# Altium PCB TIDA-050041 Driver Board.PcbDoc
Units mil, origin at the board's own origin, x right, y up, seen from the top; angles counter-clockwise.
Board outline 3950.03 x 2770.03 mil, 2 copper layers (Top Layer, Bottom Layer), stack 62 mil thick; 45 components, 22 nets, 112 pads, 128 vias.
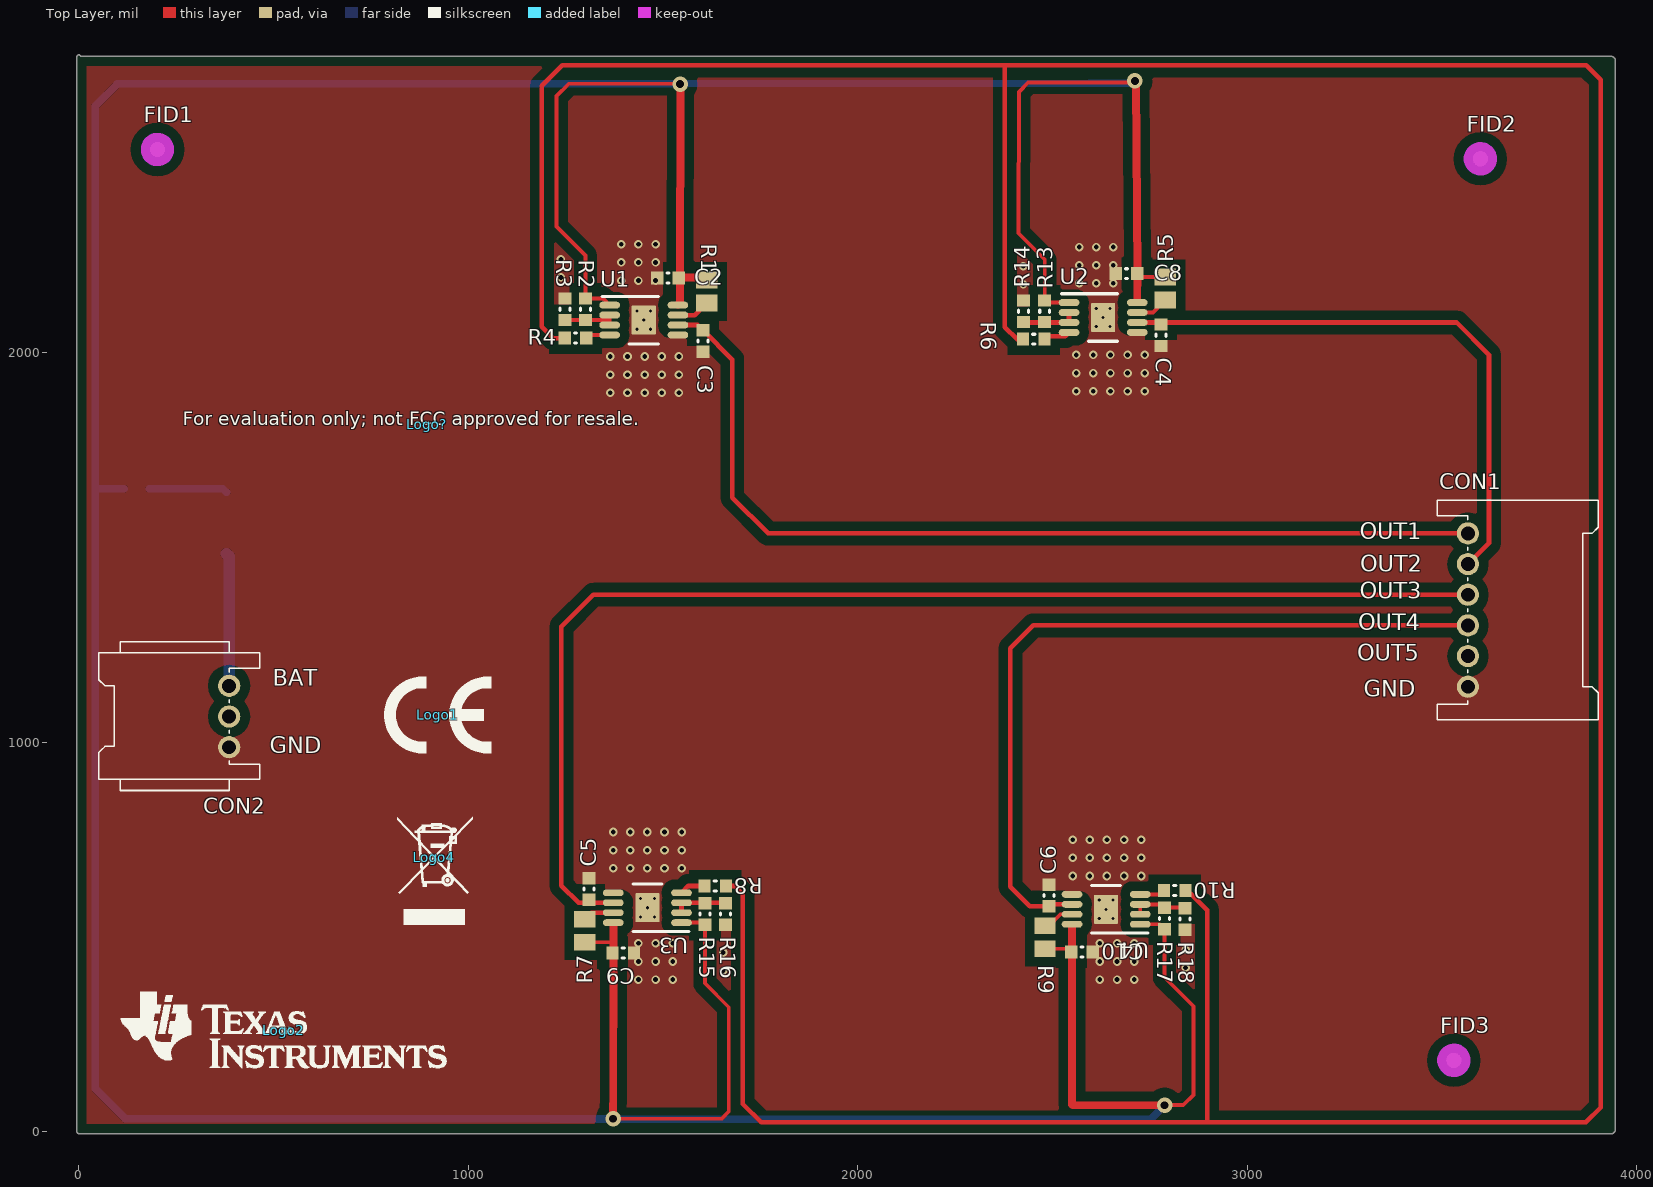
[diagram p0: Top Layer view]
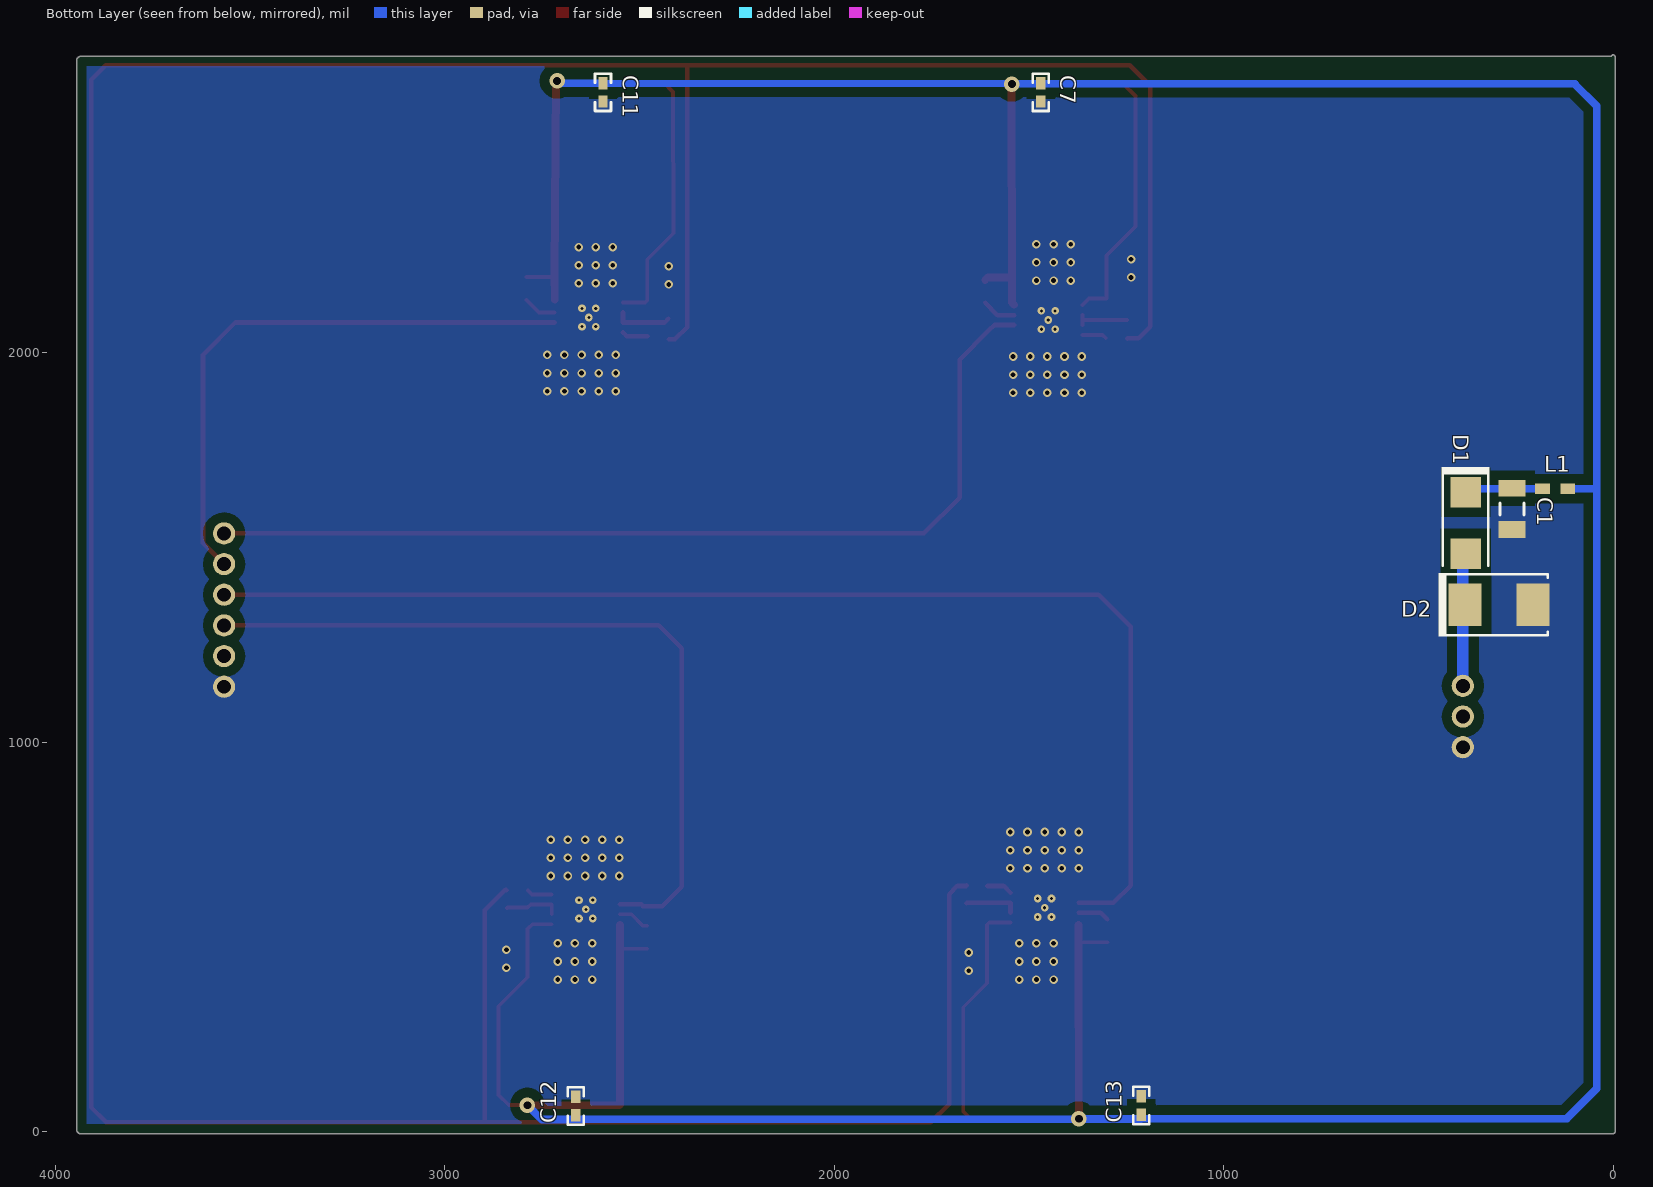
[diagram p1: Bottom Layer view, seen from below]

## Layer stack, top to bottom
Top Solder: solder mask 0.4, Solder Resist, Dk 3.5
Top Layer: signal copper 1.4
Dielectric1: core 59.2, FR-4, Dk 4.8
Bottom Layer: signal copper 1.4
Bottom Solder: solder mask 0.4, Solder Resist, Dk 3.5

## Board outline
0,-5.02 cw(c0,0) -5.01,0 -5.01,2760 cw(c0,2760) 4.93,2760.92 3937.01,2760.92 cw(c3937.01,2755.91) 3941.72,2757.62 cw(c3940,2752.91) 3945.02,2752.91 3945.02,2.99 cw(c3940,2.99) 3941.72,-1.72 cw(c3937.01,0) 3937.01,-5.02

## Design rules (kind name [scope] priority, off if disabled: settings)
AcuteAngle [All] p1: minimum=4.50000000000000E+0001 checktracksonly=FALSE
AssemblyTestPointUsage [All] p1: valid=2
BoardOutlineClearance BoardOutlineClearance_MountingHoles [OnCopper and InComponentClass('Mounting Holes')] p1: gap=40 ignorepadtopadclearanceinfootprint=FALSE
BoardOutlineClearance BoardOutlineClearance_Poly [OnCopper and IsPoly] p2: gap=25 ignorepadtopadclearanceinfootprint=FALSE
BoardOutlineClearance [OnCopper and Not InComponentClass('Logo') and not InComponentClass('FiducialMark') and not InRegion(1000,500,4000,800) and not InPoly] p3: gap=30 ignorepadtopadclearanceinfootprint=FALSE
Clearance Clearance_Keepouts [((IsTrack Or IsArc) And Not InPoly) And IsFree and IsKeepOut vs ((IsTrack Or IsArc) And Not InPoly) And IsFree and IsKeepOut] p1: gap=0 ignorepadtopadclearanceinfootprint=FALSE
Clearance Clearance_Poly [InPolygon] p2: gap=25 ignorepadtopadclearanceinfootprint=FALSE except(0: Arc-Hole Track-Hole SMDPad-Hole THPad-Hole Via-Hole Fill-Hole Poly-Hole Region-Hole Text-Hole)
Clearance Clearance_FiducialMark [IsKeepOut and InComponentClass('FiducialMark') vs IsPad and InComponentClass('FiducialMark')] p3: gap=0 ignorepadtopadclearanceinfootprint=FALSE
Clearance [All] p4: gap=7.87 ignorepadtopadclearanceinfootprint=FALSE except(0: Arc-Hole Track-Hole SMDPad-Hole THPad-Hole Via-Hole Fill-Hole Poly-Hole Region-Hole Text-Hole)
ComponentClearance ComponentClearance_MountingHoles_FiducialMarks [InComponentClass('Mounting Holes') vs InComponentClass('FiducialMark')] p1: gap=50 collisioncheckmode=3 verticalgap=10 showdistances=FALSE
ComponentClearance ComponentClearance_Shunt [InComponentClass('Header') vs InComponentClass('Shunt')] p2: gap=0 collisioncheckmode=3 verticalgap=0 showdistances=FALSE
ComponentClearance ComponentClearance_Logo [InComponentClass('Logo')] p3: gap=50 collisioncheckmode=3 verticalgap=10 showdistances=FALSE
ComponentClearance ComponentClearance_ScrewToNut [(HasFootprint('NY PMS 440 0025 PH')) vs (HasFootprint('Keystone_1902C'))] p4: gap=5 collisioncheckmode=3 verticalgap=10 showdistances=FALSE
ComponentClearance ComponentClearance_MountingHoles [InComponentClass('Mounting Holes')] p5: gap=250 collisioncheckmode=3 verticalgap=100000 showdistances=FALSE
ComponentClearance ComponentClearance_SmallPassives [HasFootprint('0201*') or HasFootprint('0402*') or HasFootprint('0508') or HasFootprint('0603*') or HasFootprint('0612') or HasFootprint('0805*') or HasFootprint('0815*') or HasFootprint('0830*') or HasFootprint('1206*') or HasFootprint('1210*') or HasFootprint('1808*') or HasFootprint('1812*') or HasFootprint('1825*') or HasFootprint('2010*') or HasFootprint('2220*') or HasFootprint('2225*') or HasFootprint('2512*') or HasFootprint('2728*') or HasFootprint('3518*') vs HasFootprint('0201*') or HasFootprint('0402*') or HasFootprint('0508') or HasFootprint('0603*') or HasFootprint('0612') or HasFootprint('0805*') or HasFootprint('0815*') or HasFootprint('0830*') or HasFootprint('1206*') or HasFootprint('1210*') or HasFootprint('1808*') or HasFootprint('1812*') or HasFootprint('1825*') or HasFootprint('2010*') or HasFootprint('2220*') or HasFootprint('2225*') or HasFootprint('2512*') or HasFootprint('2728*') or HasFootprint('3518*')] p6: gap=14.96 collisioncheckmode=3 verticalgap=10 showdistances=FALSE
ComponentClearance ComponentClearance_THtoSMT [IsThruComponent vs IsSMTComponent] p7: gap=40 collisioncheckmode=3 verticalgap=30 showdistances=FALSE
ComponentClearance ComponentClearance_THtoTH [IsThruComponent vs IsThruComponent] p8: gap=30 collisioncheckmode=3 verticalgap=30 showdistances=FALSE
ComponentClearance [All] p9: gap=30 collisioncheckmode=3 verticalgap=10 showdistances=FALSE
DiffPairsRouting [All] p1: maxlimit=100 minlimit=10 mostfreqgap=10 toplayer_minwidth=15 toplayer_maxwidth=15 toplayer_prefwidth=15 bottomlayer_minwidth=15 bottomlayer_maxwidth=15 bottomlayer_prefwidth=15 maxuncoupledlength=1000
FabricationTestPointUsage TestPointUsage [All] p1: valid=2 allowmultiple=FALSE
FabricationTestpoint Testpoint [All] p1: side=3 testpointundercomponent=TRUE minsize=40 maxsize=100 preferedsize=60 minholesize=0 maxholesize=40 preferedholesize=32 testpointgrid=1 allowsidetop=TRUE allowsidebottom=TRUE usegrid=TRUE gridtolerance=0.01
FanoutControl Fanout_LCC [IsLCC] p1: bgadir=Out bgaviamode=Centered fanoutstyle=Auto fanoutdirection=Alternating viagrid=1 // Fanout_LCC (Default Rule)
FanoutControl Fanout_BGA [IsBGA] p2: bgadir=Out bgaviamode=Centered fanoutstyle=Auto fanoutdirection=Alternating viagrid=1 // Fanout_BGA (Default Rule)
FanoutControl Fanout_Default [All] p4: bgadir=Out bgaviamode=Centered fanoutstyle=Auto fanoutdirection=Alternating viagrid=1 // Fanout_Default (Default Rule)
FanoutControl Fanout_Small [(CompPinCount < 5)] p5: bgadir=Out bgaviamode=Centered fanoutstyle=Auto fanoutdirection=OutThenIn viagrid=1 // Fanout_Small (Default Rule)
HoleSize [All] p1: absolutevalues=TRUE maxlimit=251 minlimit=7.87 maxpercent=80.000 minpercent=20.000
MinimumAnnularRing MinimumAnnularRing_ThermalPadVias [IsVia and InAnyComponent] p1: minimumring=5.91
MinimumAnnularRing [All] p2: minimumring=8
MinimumSolderMaskSliver MinimumSolderMaskSliver_Logo [InComponentClass('Logo') vs InComponentClass('Logo')] p1: minsoldermaskwidth=0.7
MinimumSolderMaskSliver [All] p2: minsoldermaskwidth=3.94
PlaneConnect [All] p1: planeconnectstyle=Direct reliefexpansion=10 reliefentries=4 reliefconductorwidth=10 reliefairgap=10
PolygonConnect [All] p1: connectstyle=Direct reliefconductorwidth=10 reliefentries=4 polygonreliefangle="90 Angle" airgapwidth=10
RoutingVias ThermalPadVias [IsVia and InAnyComponent] p1: holewidth=7.87 width=19.68 viastyle="Through Hole" minholewidth=7.87 minwidth=19.68 maxholewidth=12.99 maxwidth=23.62
RoutingVias [All] p2: holewidth=16 width=34 viastyle="Through Hole" minholewidth=7.87 minwidth=26 maxholewidth=40 maxwidth=65
SilkToBoardRegionClearance [Not ((IsComment or IsDesignator) And (Hide <> 'False')) and not InRegion(1000,500,4000,800)] p1:
SilkToSilkClearance SilkToSilkClearance_Pb-FreeLogo [(HasFootprint('Pb-Free_Overlay_Medium') OR HasFootprint('Pb-Free_Overlay_Small')) vs (HasFootprint('Pb-Free_Overlay_Medium') OR HasFootprint('Pb-Free_Overlay_Small'))] p1: silktosilkclearance=0
SilkToSilkClearance [All] p2: silktosilkclearance=4
SilkToSolderMaskClearance SilkToComponentPadClearance [(IsPad or IsFill or IsRegion) and InAnycomponent] p1: minsilkscreentomaskgap=5 clearancetoexposedcopper=TRUE
SilkToSolderMaskClearance "Silk to Solder Mask Opening" [All] p2: minsilkscreentomaskgap=4 clearancetoexposedcopper=FALSE
SolderMaskExpansion [All] p1: expansion=1.97
Width [All] p1: maxlimit=100 minlimit=6 preferedwidth=10 checkconnectedcopper=TRUE
15 further rules are at their usual default settings.

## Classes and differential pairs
component class Sheet1: FID1 FID2 FID3 Logo1 Logo2 Logo4 Logo?
component class Logo: Logo2
component class FiducialMark: FID1 FID2 FID3
component class "TIDA-050041 Driver Board": C1 C2 C3 C4 C5 C6 C7 C8 C9 C10 C11 C12 C13 CON1 CON2 D1 D2 L1 R1 R2 R3 R4 R5 R6 R7 R8 R9 R10 R13 R14 R15 R16 R17 R18 U1 U2 U3 U4

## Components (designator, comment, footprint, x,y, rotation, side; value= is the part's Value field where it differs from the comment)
C1 "GRM319R61H475KA12" 1206L 260,1599 r270 bottom value=4.7uF
C2 "CGA3E3X8R1H104K080AE" 0603L 1513,2192 r180 top value=0.1uF
C3 "CGA3E3X8R1H104K080AE" 0603L 1603,2030.13 r270 top value=0.1uF
C4 "CGA3E3X8R1H104K080AE" 0603L 2779,2045 r270 top value=0.1uF
C5 "CGA3E3X8R1H104K080AE" 0603L 1310,623 r90 top value=0.1uF
C6 "CGA3E3X8R1H104K080AE" 0603L 2491.4,606.55 r90 top value=0.1uF
C7 "GRM155R71H471KA01D" 0402 1470,2668.62 r270 bottom value=470pF
C8 "CGA3E3X8R1H104K080AE" 0603L 2690,2203 r180 top value=0.1uF
C9 "CGA3E3X8R1H104K080AE" 0603L 1398,459 r0 top value=0.1uF
C10 "CGA3E3X8R1H104K080AE" 0603L 2576,461 r0 top value=0.1uF
C11 "GRM155R71H471KA01D" 0402 2594,2668.62 r270 bottom value=470pF
C12 "GRM155R71H471KA01D" 0402 2664,66 r90 bottom value=470pF
C13 "GRM155R71H471KA01D" 0402 1212,67 r90 bottom value=470pF
CON1 "SWB-3535WR-06B-NOSN" "SWB-3535 WR-06P" 3567,1142.52 r90 top
CON2 "SWB-3535WR-03B-NOSN" "SWB-3535 WR-03P" 386,1066 r270 top
D1 "S1A" SMA 379,1563 r270 bottom value=50V
D2 "SMBJ30CA-13-F" SMB 293,1353 r180 bottom value=30V
FID1 "Fiducial" Fiducial10-20 202,2522 r0 top
FID2 "Fiducial" Fiducial10-20 3599,2498 r0 top
FID3 "Fiducial" Fiducial10-20 3531,183 r0 top
L1 "74279266A" WE-CBF_0603 149,1651 r180 bottom value="1000 ohm"
Logo1 "CE Mark" CE_Mark_5mm 921.85,1070 r0 top
Logo2 "Texas Instruments" TI_Stacked_Overlay_Small 526,261 r0 top
Logo4 "WEEE logo" WEEE_Minimum 912.76,704 r0 top
Logo? "FCC disclaimer" FCC_disclaimer 894,1816 r0 top
R1 "RMCF0805FT1R00" 0805L 1612.37,2157.65 r270 top value=1.00
R2 "RC0603FR-0775KL" 0603L 1301.37,2111.65 r90 top value=75.0k
R3 "CRCW060320K0FKEA" 0603L 1248.37,2111.65 r270 top value=20.0k
R4 "ERJ-3GEY0R00V" 0603L 1275.37,2037.65 r180 top value=0
R5 "RMCF0805FT1R00" 0805L 2790.28,2164.62 r270 top value=1.00
R6 "ERJ-3GEY0R00V" 0603L 2452.28,2034.83 r180 top value=0
R7 "RMCF0805FT1R00" 0805L 1299,516 r90 top value=1.00
R8 "ERJ-3GEY0R00V" 0603L 1634.5,630.95 r0 top value=0
R9 "RMCF0805FT1R00" 0805L 2481,499.06 r90 top value=1.00
R10 "ERJ-3GEY0R00V" 0603L 2814.4,619.55 r0 top value=0
R13 "RC0603FR-0775KL" 0603L 2480.28,2106.62 r90 top value=75.0k
R14 "CRCW060320K0FKEA" 0603L 2426.28,2106.62 r270 top value=20.0k
R15 "RC0603FR-0775KL" 0603L 1607.5,558.95 r270 top value=75.0k
R16 "CRCW060320K0FKEA" 0603L 1660.5,558.95 r90 top value=20.0k
R17 "RC0603FR-0775KL" 0603L 2787.4,547.55 r270 top value=75.0k
R18 "CRCW060320K0FKEA" 0603L 2840.4,546.31 r90 top value=20.0k
U1 "TPS92611QDGNRQ1" DGN0008D_N 1450.68,2084 r0 top
U2 "TPS92611QDGNRQ1" DGN0008D_N 2630.28,2090.62 r0 top
U3 "TPS92611QDGNRQ1" DGN0008D_N 1460,575 r180 top
U4 "TPS92611QDGNRQ1" DGN0008D_N 2638,571 r180 top

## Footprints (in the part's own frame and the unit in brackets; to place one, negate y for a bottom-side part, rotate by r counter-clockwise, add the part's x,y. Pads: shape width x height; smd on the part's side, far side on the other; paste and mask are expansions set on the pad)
0402 [mm] "0402 from SM-752 data"
  rect 0.8x0.6 smd: 1(-0.6,0) 2(0.6,0)
  silkscreen extent -1.22,-0.52 1.22,0.52, body extent -0.55,-0.3 0.55,0.3, height 0.6
0603L [mm] "0603 from SM-752 data"
  rect 0.8x0.85 smd: 1(-0.7,0) 2(0.7,0)
  silkscreen extent -0.07,-0.33 0.07,0.33, body extent -0.87,-0.47 0.87,0.47, height 1
0805L [mm] "0805 from SM-752 data"
  rect 1.1x1.4 smd: 1(-0.75,0) 2(0.75,0)
  body extent -1.1,-0.72 1.1,0.72, height 1.45
1206L [mm] "1206 from SM-752 data"
  rect 1.1x1.75 smd: 1(-1.35,0) 2(1.35,0)
  silkscreen extent -0.4,-0.77 0.4,0.77, body extent -1.7,-0.9 1.7,0.9, height 1.35
CE_Mark_5mm [mil] "Minimum text height for CE Mark"
  silkscreen extent -138,-98 138,98
DGN0008D_N [mm] "TSOP, 8-Leads, Body 3x3mm, Pitch 0.65mm, Thermal Pad 1.89x1.57mm, IPC Medium Density"
  rrect100% 1.35x0.45 smd: 1(-2.225,0.975) 2(-2.225,0.325) 3(-2.225,-0.325) 4(-2.225,-0.975) 5(2.225,-0.975) 6(2.225,-0.325) 7(2.225,0.325) 8(2.225,0.975)
  rrect6% 1.57x1.89 smd: 9(0,0)
  silkscreen extent -2.73,-1.55 0.95,1.55, body extent -2.46,-1.5 2.46,1.5, height 1.1
FCC_disclaimer [mil]
Fiducial10-20 [mm]
  round 1 smd mask+0.5: 1(0,0)
  Top Layer keep-out circle w1.178: c0,0 r0.5
SMA [mm] "Molded Diode, 2-Leads, Body 4.3x2.6mm, IPC Medium Density, based on OnSemi component dimensions and land pattern"
  rect 2x2 smd: 1(-2,0) 2(2,0)
  silkscreen extent -3.66,-1.57 2.79,1.57, body extent -2.6,-1.3 2.6,1.3, height 2.42
SMB [mil] "Molded Diode, 2-Leads, Body 5.4x3.6mm, IPC Medium Density, based on OnSemi component dimensions"
  rect 85x107.99 smd: 1(-87.01,0) 2(87.01,0)
  silkscreen extent -155,-82 125,82, body extent -106,-71 106,71, height 91
"SWB-3535 WR-03P" [mm]
  round 1.45 hole 0.9: 1(-2,0) 2(0,0) 3(2,0)
  silkscreen extent -4.88,-8.5 4.83,2, body extent -4.85,-8.5 4.85,2, height 5.65
"SWB-3535 WR-06P" [mm]
  round 1.45 hole 0.9: 1(0,0) 2(2,0) 3(4,0) 4(6,0) 5(8,0) 6(10,0)
  silkscreen extent -2.15,-8.5 12.15,2, body extent -2.15,-8.5 12.15,2, height 5.65
TI_Stacked_Overlay_Small [mil]
  silkscreen extent -418,-98 418,98
WE-CBF_0603 [mm] "WE_SMT-0603"
  rect 0.95x0.7 smd: 1(-0.825,0) 2(0.825,0)
  body extent -0.9,-0.5 0.9,0.5, height 1
WEEE_Minimum [mil] "WEEElie bin"
  silkscreen extent -95,-172 99,104

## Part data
C1: library part CMP-0008865-2, "CAP, CERM, 4.7 uF, 50 V, +/- 10%, X5R, 1206", Cap_Case=1206, Manufacturer=MuRata, Supplier Part Number 1=13T1225, TempCo=X5R, Tolerance_%=10%, Value1=Unknown, Value2=50V, ValueDisplayed=4.7uF
C2 C3 C4 C5 C6 C8 C9 C10: library part CMP-0079911-1, "CAP, CERM, 0.1 礔, 50 V,+/- 10%, X8R, AEC-Q200 Grade 0, 0603", Cap_Case=0603, Manufacturer=TDK, Supplier Part Number 1=445-173697-1-ND, TempCo=X8R, Tolerance_%=10%, Value2=50V, ValueDisplayed=0.1礔
C7 C11 C12 C13: library part CMP-0006691-2, "CAP, CERM, 470 pF, 50 V, +/- 10%, X7R, 0402", Cap_Case=0402, Manufacturer=MuRata, Supplier Part Number 1=490-1300-1-ND, TempCo=X7R, Tolerance_%=10%, Value1=Unknown, Value2=50V, ValueDisplayed=470pF
CON1 CON2: 供覽]商/品牌 Manufacturer=SWB
D1: library part CMP-0082549-1, "Diode, Standard Recovery Rectifier, 50 V, 1 A, SMA", Manufacturer="ON Semiconductor", Supplier Part Number 1=S1AFSCT-ND, Value1=1A, Value2=1.1V
D2: library part CMP-0005562-2, "Diode, TVS, Bi, 30 V, SMB", Manufacturer="Diodes Inc.", Power_W=5W, Supplier Part Number 1=SMBJ30CA-FDICT-ND
FID1 FID2 FID3: library part CMP-0077181-1, "Fiducial mark.  There is nothing to buy or mount.", Manufacturer=N/A
L1: library part CMP-0003204-1, "Ferrite Bead, 1000 ohm @ 100 MHz, 0.2 A, 0603", Manufacturer="Wurth Elektronik", Supplier Part Number 1=732-1598-1-ND, Value1="0.6 ohm", Value2=0.2A, ValueDisplayed="1000 ohm"
Logo1: library part CMP-0074844-1
Logo2: library part CMP-0074838-1, "Texas Instrument Corporate Signature"
Logo4: library part CMP-0074769-1
Logo?: library part CMP-0074847-1, "FCC_disclaimer"
R1 R5 R7 R9: library part CMP-0021975-2, "RES, 1.00, 1%, 0.125 W, 0805", Manufacturer="Stackpole Electronics Inc", Power_W=125mW, Supplier Part Number 1=RMCF0805FT1R00DKR-ND, TempCo="200 ppm/C", Tolerance_%=1%, Value2=0.125W, Value_Code=1R00, ValueDisplayed=1.00
R2 R13 R15 R17: library part CMP-0023267-5, "RES, 75.0 k, 1%, 0.1 W, 0603", Manufacturer=Yageo, Power_W=100mW, Supplier Part Number 1=311-75.0KHRCT-ND, TempCo="100 ppm/C", Tolerance_%=1%, Value2=0.1W, Value_Code=75k0, ValueDisplayed=75.0k
R3 R14 R16 R18: library part CMP-0022204-4, "RES, 20.0 k, 1%, 0.1 W, AEC-Q200 Grade 0, 0603", Manufacturer=Vishay-Dale, Power_W=100mW, Supplier Part Number 1=541-20.0KHCT-ND, TempCo="100 ppm/C", Tolerance_%=1%, Value2=0.1W, Value_Code=20k0, ValueDisplayed=20.0k
R4 R6 R8 R10: library part CMP-0025874-4, "RES, 0, 5%, 0.1 W, AEC-Q200 Grade 0, 0603", Manufacturer=Panasonic, Power_W=100mW, Supplier Part Number 1=P0.0GCT-ND, TempCo="600 ppm/C", Tolerance_%=5%, Value2=0.1W, Value_Code=0000, ValueDisplayed=0
U1 U2 U3 U4: library part CMP-0065147-2, "Automotive Single Channel LED Driver, DGN0008D (VSSOP-8)", Alternate Manufacturer="Texas Instruments"

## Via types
v1: diameter 22, hole 12, Top Layer to Bottom Layer, 104 vias
v2: diameter 19.68, hole 7.87, Top Layer to Bottom Layer, 20 vias
v3: diameter 40, hole 20, Top Layer to Bottom Layer, 4 vias

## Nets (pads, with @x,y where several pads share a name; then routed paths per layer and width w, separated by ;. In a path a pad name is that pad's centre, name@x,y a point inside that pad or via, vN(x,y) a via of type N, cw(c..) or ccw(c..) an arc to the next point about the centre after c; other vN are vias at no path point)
BAT: CON2.1 D1.2 D2.1 | length 342.4
  Bottom Layer w30: D1.2 386,1477.26 CON2.1
GND: C1.2 C2.2 C3.2 C4.2 C5.2 C6.2 C7.2 C8.2 C9.2 C10.2 C11.2 C12.2 C13.2 CON1.1 CON2.3 D2.2 R3.1 R14.1 R16.1 R18.1 U1.5 U1.9 U2.5 U2.9 U3.5 U3.9 U4.5 U4.9
  other v1: 1437,390.5 1481,390.5 1525,390.5 2622,390.5 2666,390.5 2710,390.5 1655,413.5 2841.96,420.5 1437,437 1481,437 1525,437 2622,437 2666,437 2710,437 1655,460 2841.96,467 1437,483.5 1481,483.5 1525,483.5 2622,483.5 2666,483.5 2710,483.5 2552,656.5 2596,656.5 2640,656.5 2684,656.5 2728,656.5 1372,676.5 1416,676.5 1460,676.5 1504,676.5 1548,676.5 2552,703 2596,703 2640,703 2684,703 2728,703 1372,723 1416,723 1460,723 1504,723 1548,723 2552,749.5 2596,749.5 2640,749.5 2684,749.5 2728,749.5 1372,769.5 1416,769.5 1460,769.5 1504,769.5 1548,769.5 1365,1897.5 1409,1897.5 1453,1897.5 1497,1897.5 1541,1897.5 2561,1901.5 2605,1901.5 2649,1901.5 2693,1901.5 2737,1901.5 1365,1944 1409,1944 1453,1944 1497,1944 1541,1944 2561,1948 2605,1948 2649,1948 2693,1948 2737,1948 1365,1990.5 1409,1990.5 1453,1990.5 1497,1990.5 1541,1990.5 2561,1994.5 2605,1994.5 2649,1994.5 2693,1994.5 2737,1994.5 2425,2175.5 2568.57,2178.5 2612.57,2178.5 2656.57,2178.5 1393,2185.5 1437,2185.5 1481,2185.5 1238,2193.5 2425,2222 2568.57,2225 2612.57,2225 2656.57,2225 1393,2232 1437,2232 1481,2232 1238,2240 2568.57,2271.5 2612.57,2271.5 2656.57,2271.5 1393,2278.5 1437,2278.5 1481,2278.5
  other v2: 2620.28,547.38 2655.72,547.38 1442.28,551.38 1477.72,551.38 2638,571 1460,575 2620.28,594.62 2655.72,594.62 1442.28,598.62 1477.72,598.62 1432.97,2060.38 1468.4,2060.38 2612.57,2067 2648,2067 1450.68,2084 2630.28,2090.62 1432.97,2107.62 1468.4,2107.62 2612.57,2114.24 2648,2114.24
IN: C2.1 C7.1 C8.1 C9.1 C10.1 C11.1 C12.1 C13.1 L1.2 R1.1 R2.2 R5.1 R7.1 R9.1 R13.2 R15.2 R17.2 U1.1 U1.8 U2.1 U2.8 U3.1 U3.8 U4.1 U4.8 | length 14069.3
  Top Layer w10: R7.1 1372.37,486.47 1372.84,486 ; U1.1 1346.27,2139.2 R2.2 1301.37,2249.63 1227,2324 1227,2659 1258.88,2690.88 1542.05,2690.88 v3@1543.93,2689 ; v3(1372,33) 1650.53,33 1669,51.47 1669,319.5 1607.5,381 R15.2 1602.28,536.61 U3.1 ; R9.1 2539.91,469.54 C10.1 ; U2.1 2485.46,2129.01 R13.2 2480.28,2239.72 2413,2307 2414,2670 2438,2694 v3@2715,2694 ; 2550.4,70 2552.4,68 ; C8.1 2718.25,2202.31 2726.41,2194.15 R5.1 ; U4.1 2774.78,532.61 R17.2 2787.4,396.6 2862,322 2862,94 2836,68 v3(2788,68)
  Top Layer w20: U3.8@1372.89,530.71 1372.84,486 1372.81,459 1372.4,71.4 1372,71 1372,41 v3@1374,39 ; U1.8@1538.28,2123.53 1543.93,2129.17 1544.05,2191.99 1544.05,2193.65 1544.05,2193.77 1544.93,2654.7 v3@1543.93,2689 ; C2.1@1545.93,2195.65 1543.93,2193.65 1605.9,2193.65 R1.1 ; 2550.4,70 U4.8@2550.4,531.47 ; 2552.4,68 v3(2788,68) ; v3@2715,2694 2718.25,2203 2718.25,2202.31 U2.8@2718,2137
  Bottom Layer w20: L1.2 42,1651 ; v3(2712,2698) 2706,2692 2647,2692 2594,2691.96 1544,2691.08 1470,2691.02 98.25,2689.87 42,2633.62 42,1651 ; v3(2788,68) 2751,31 2743,31 2663.99,31.09 1372,32.57 1211.99,32.75 118.7,34 42,110.7 42,1651
  other v3: 1544,2690
NetC1_1: C1.1 D1.1 L1.1 | length 201.4
  Bottom Layer w20: L1.1 369.74,1651 D1.1
NetR1_2: R1.2 U1.7 | length 87.1
  Top Layer w12: U1.7 1581.05,2096.8 R1.2
NetR2_1: R2.1 R3.2 U1.2 U1.3 | length 140.7
  Top Layer w10: R3.2 R2.1 1362.17,2084.09 1363.09,2085 ; U1.3 1363.09,2085 ; U1.2 1363.09,2085
NetR4_1: R4.1 U1.4 | length 63.5
  Top Layer w10: R4.1 1310.9,2045.61 U1.4
NetR4_2: R4.2 R6.2 R8.2 R10.2 | length 10273
  Top Layer w12: R4.2@1247,2036.83 R4.2 1218.35,2037.65 1189,2067 1189,2686 1241,2738 2378,2738 ; R8.2@1660.5,632.51 R8.2 1684.05,630.95 1705,610 1705,71 1752,24 2901,24 ; R6.2 2409.17,2034.83 2378,2066 2378,2738 ; R10.2@2843,620.59 R10.2 2846.82,619.55 2897.37,569 2897.37,27.63 2901,24 ; 2378,2738 3871,2738 3908,2701 3908,62 3870,24 2901,24
NetR5_2: R5.2 U2.7 | length 85.5
  Top Layer w10: U2.7 2758.61,2103.42 R5.2
NetR6_1: R6.1 U2.4 | length 66.7
  Top Layer w12: R6.1@2479.84,2042.83 2533.28,2042.83 U2.4
NetR7_2: R7.2 U3.7 | length 80.3
  Top Layer w12: R7.2 1315.68,562.2 U3.7
NetR8_1: R8.1 U3.4 | length 66.6
  Top Layer w12: U3.4 1565.17,630.95 R8.1
NetR9_2: R9.2 U4.7 | length 81.7
  Top Layer w10: R9.2 2491.69,528.59 2521.3,558.2 U4.7
NetR10_1: R10.1 U4.4 | length 65.5
  Top Layer w10: U4.4 2776.68,609.39 R10.1
NetR13_1: R13.1 R14.2 U2.2 U2.3 | length 145.8
  Top Layer w12: R14.2@2426.28,2087.06 2435.52,2077.83 U2.3 U2.2
NetR15_1: R15.1 R16.2 U3.2 U3.3 | length 139
  Top Layer w12: U3.2 U3.3 1659.22,587.8 R16.2
NetR17_1: R17.1 R18.2 U4.2 U4.3 | length 144.5
  Top Layer w10: U4.2 U4.3 2778.72,583.8 R17.1 2839.16,575.11 R18.2
OUT1: C3.1 CON1.6 U1.6 | length 2458.1
  Top Layer w12: U1.6 1589.48,2071.2 C3.1 1678,1982.69 1678,1628 1769.78,1536.22 CON1.6
OUT2: C4.1 CON1.5 U2.6 | length 1497.3
  Top Layer w12: U2.6 3538.17,2077.83 3621,1995 3621,1511.48 CON1.5
OUT3: C5.1 CON1.4 U3.6 | length 3178.6
  Top Layer w12: U3.6 1283.2,587.8 1239,632 1239,1297 1320.74,1378.74 CON1.4
OUT4: C6.1 CON1.3 U4.6 | length 1992.5
  Top Layer w12: U4.6 2496.2,583.8 C6.1 2442.01,578.99 2392,629 2392,1241 2451,1300 CON1.3
OUT5: CON1.2
pads on no net: CON2.2 FID1.1 FID2.1 FID3.1

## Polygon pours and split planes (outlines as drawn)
GND on Bottom Layer "Top Layer-No Net1" (solid, remove dead copper, pour order 3): 0,-5.02 cw(c0,0) -5.01,0 -5.01,2760 cw(c0,2760) 4.93,2760.92 3937.01,2760.92 cw(c3937.01,2755.91) 3941.72,2757.62 cw(c3940,2752.91) 3945.02,2752.91 3945.02,2.99 cw(c3940,2.99) 3941.72,-1.72 cw(c3937.01,0) 3937.01,-5.02
GND on Top Layer "Top Layer-No Net" (solid, remove dead copper, pour order 2): 0,-5.02 cw(c0,0) -5.01,0 -5.01,2760 cw(c0,2760) 4.93,2760.92 3937.01,2760.92 cw(c3937.01,2755.91) 3941.72,2757.62 cw(c3940,2752.91) 3945.02,2752.91 3945.02,2.99 cw(c3940,2.99) 3941.72,-1.72 cw(c3937.01,0) 3937.01,-5.02

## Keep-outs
Keep-Out Layer:
  text ".Layer_Name" at 577,-858.49 h60

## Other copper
Top Layer:
  text ".Layer_Name" at 577,-858.49 h60
Bottom Layer:
  text ".Layer_Name" at 577,-858.49 h60

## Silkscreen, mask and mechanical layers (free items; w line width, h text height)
Top Overlay:
  text "OUT1" at 3289,1507 h72.83
  text "OUT2" at 3291,1424 h72.83
  text "OUT3" at 3289,1354 h72.83
  text "OUT4" at 3286,1273 h72.83
  text "OUT5" at 3283,1195 h72.83
  text "BAT" at 498,1131 h72.83
  text "GND" at 3299,1102 h72.83
  text "GND" at 490,958 h72.83
  text ".Layer_Name" at 577,-858.49 h60
Bottom Overlay:
  text ".Layer_Name" at 577,-858.49 h60
Top Paste:
  text ".Layer_Name" at 577,-858.49 h60
Bottom Paste:
  text ".Layer_Name" at 577,-858.49 h60
Top Solder:
  text ".Layer_Name" at 577,-858.49 h60
  text ".Layer_Name" at 577,-858.49 h60
Bottom Solder:
  text ".Layer_Name" at 577,-858.49 h60
Drill Guide:
  text ".Layer_Name" at 577,-858.49 h60
M1 Board Outline:
  lines w10: 0,0 3937.01,0 3940,2.99 3940,2752.91 3937.01,2755.91 4.09,2755.91 0,2760 0,0
  text ".Layer_Name" at 577,-858.49 h60
M2 Board Dimensions:
  rectangle: 125,-400 500,-275
  rectangle: 0,-275 125,-150
  lines w7: 0,-275 1000,-275 ; 125,-400 125,-150 ; 250,-400 250,-150 ; 500,-400 500,-150 ; 750,-400 750,-150 ; 0,-400 0,-150 1000,-150 1000,-400 0,-400
  text ".Layer_Name" at 577,-858.49 h60
M3 3D STEP Top:
  text ".Layer_Name" at 577,-858.49 h60
M4 3D STEP Bottom:
  text ".Layer_Name" at 577,-858.49 h60
M5 Assembly Top:
  lines w10: -292,-930.17 6308,-930.17 ; -292,-726.83 6310,-726.83 ; -292,-523.5 -292,-1133.5 3713,-1133.5 6310,-1133.5 6310,-523.5 -291.5,-523.5 -291.5,-1133.5 1284,-1133.5 ; 2173,-1133.5 2173,-523.5 ; 3440,-726.83 3440,-523.5 ; 4280,-726.83 4280,-523.5 ; 4902,-1140 4902,-937.17
  text "COMPONENTS MARKED 'DNP' SHOULD NOT BE POPULATED." at 1153.5,-318.5 h60
  text "ASSEMBLY VARIANT:" at 1153,-434 h60
  text ".VariantName" at 2189,-434 h60
  text "PCB VIEWED FROM TOP SIDE" at -228.5,-655.67 h60
  text "BOARD #:" at 2248,-655.67 h60
  text ".PRJ_Number" at 2793.5,-655.67 h60
  text "REV:" at 3638,-655.67 h60
  text ".PCB_Rev" at 3929.5,-655.67 h60
  text "SVN REV:" at 4476,-655.67 h60
  text ".VersionControl_RevNumber" at 4982,-655.67 h60
  text "TID #:" at 2248,-859 h60
  text ".TID" at 2793.5,-859 h60
  text "PLOT NAME =" at -228.5,-1064.34 h60
  text ".plot_File_Name" at 577,-1064.34 h60
  text "GENERATED    :" at 2250,-1064.34 h60
  text ".Print_Date" at 3119.5,-1064.34 h60
  text ".Print_Time" at 3848.5,-1064.34 h60
  text "TEXAS INSTRUMENTS" at 5113,-1064.34 h60
M6 Assembly Bottom:
  lines w10: -292.5,-727.33 6309.5,-727.33 ; -290.5,-930.67 6309.5,-930.67 ; 1115.5,-1140.5 1115.5,-937.67 ; 1737.5,-727.33 1737.5,-524 ; 2577.5,-727.33 2577.5,-524 ; 3844.5,-1134 3844.5,-524 ; 4733.5,-1134 6309,-1134 6309,-524 -292.5,-524 -292.5,-1134 2304.5,-1134 6309.5,-1134 6309.5,-524
  text "COMPONENTS MARKED 'DNP' SHOULD NOT BE POPULATED." at 6102,-318 h60
  text ".VariantName" at 5058,-434 h60
  text "ASSEMBLY VARIANT:" at 6097,-434 h60
  text ".VersionControl_RevNumber" at 1035.5,-656.17 h60
  text "SVN REV:" at 1541.5,-656.17 h60
  text ".PCB_Rev" at 2088,-656.17 h60
  text "REV:" at 2379.5,-656.17 h60
  text ".PRJ_Number" at 3224,-656.17 h60
  text "BOARD #:" at 3769.5,-656.17 h60
  text "PCB VIEWED FROM BOTTOM SIDE" at 6246,-656.17 h60
  text ".TID" at 3224,-859.5 h60
  text "TID #:" at 3769.5,-859.5 h60
  text "TEXAS INSTRUMENTS" at 904.5,-1064.84 h60
  text ".Print_Time" at 2169,-1064.84 h60
  text ".Print_Date" at 2898,-1064.84 h60
  text "GENERATED    :" at 3767.5,-1064.84 h60
  text ".plot_File_Name" at 5440.5,-1064.84 h60
  text "PLOT NAME =" at 6246,-1064.84 h60
M9 Title Sheet:
  drawing of 57 lines, arcs and shapes, not listed
  text "1" at 739.84,8036.5 h70
  text "2" at 3235.5,8036.5 h70
  text "3" at 5724.84,8036.5 h70
  text "4" at 8231.51,8036.5 h70
  text "5" at 10730.5,8036.5 h70
  text "6" at 13235.5,8036.5 h70
  text "A" at -416.5,6893.5 h70
  text "A" at 14383.5,6893.5 h70
  text "B" at -416.5,4513.5 h70
  text "B" at 14383.5,4513.5 h70
  text "C" at -416.5,2138.5 h70
  text "C" at 14383.5,2138.5 h70
  text "PROJECT TITLE:" at 11343.5,277.5 h45
  text ".PRJ_Title" at 11393.5,144.17 h70
  text "DESIGNED FOR:" at 11343.5,-23.5 h45
  text ".PRJ_Customer" at 11393.5,-163.5 h70
  text "D" at -416.5,-231.5 h70
  text "D" at 14383.5,-231.5 h70
  text "FILE NAME:" at 11343.5,-323.5 h45
  text ".PCB_File_Name_No_Path" at 11393.5,-443.5 h70
  text "Texas Instruments (TI) and/or its licensors do not warrant the accuracy or completeness of this specification" at 6374,-605.34 h45
  text "ENGINEER:" at 11343.5,-613.5 h45
  text "LAYOUT BY:" at 12848.5,-613.5 h45
  text "or any information contained therein. TI and/or its licensors do not warrant that this design will meet" at 6329.01,-718 h45
  text ".PRJ_Engineer" at 11393.5,-768.49 h70
  text ".PCB_Layout" at 12899,-768.49 h70
  text "the specifications, will be suitable for your application or fit for any particular purpose, or will operate in" at 6329.01,-830.67 h45
  text ".Layer_Name" at 577,-858.49 h60
  text "ALTIUM DESIGNER VERSION:" at 12848.5,-923.5 h45
  text "an implementation. TI and/or its licensors do not warrant that the design is production worthy. You should" at 6329.01,-943.33 h45
  text "completely validate and test your design implementation to confirm the system functionality for your application." at 6374,-1056 h45
  text ".print_Scale" at 11393.5,-1056.83 h70
  text ".Application_BuildNumber" at 12899,-1056.83 h70
  text "1" at 739.84,-1263.5 h70
  text "2" at 3235.5,-1263.5 h70
  text "3" at 5724.84,-1263.5 h70
  text "4" at 8231.51,-1263.5 h70
  text "5" at 10730.5,-1263.5 h70
  text "6" at 13235.5,-1263.5 h70
M10 Fab Notes:
  drawing of 189 lines, arcs and shapes, not listed
  text "DESIGN INFORMATION" at 12382.02,6356.17 h60
  text "MIN. TRACK WIDTH:" at 11737.46,6224.05 h60
  text "8" at 12833.7,6224.05 h60
  text "MIL" at 12988.46,6224.05 h60
  text "MIN. CLEARANCE:" at 11737.46,6099.92 h60
  text "0.2" at 12773.7,6099.93 h60
  text "mm" at 12988.46,6099.92 h60
  text "MIN. VIA PAD SIZE:" at 11737.46,5975.8 h60
  text "24" at 12803.71,5975.8 h60
  text "MIL" at 12988.46,5975.8 h60
  text "0.05mm (2MIL)" at 12432.46,5845.9 h60
  text "MINIMUM ANNULAR RING" at 11408.23,5837.67 h60
  text "EXTERNAL" at 13140.46,5837.67 h60
  text "PER" at 11608.23,5727.55 h60
  text "IPC-D-275 CLASS 2 LEVEL C" at 11828.23,5727.54 h60
  text "MIL, HOLES" at 13316.46,5627.07 h60
  text "+/-" at 12924,5618.48 h60
  text "+/-" at 13778,5618.48 h60
  text "REGISTRATION TOLERANCES:" at 11408.23,5617.42 h60
  text "METAL" at 12608,5617.42 h60
  text "5" at 13184.2,5617.42 h60
  text "3" at 14017.2,5617.42 h60
  text "MIL" at 14133.46,5617.42 h60
  text "HOLE SIZE TOLERANCE (UNLESS OTHERWISE SPECIFIED):" at 11408.23,5519.1 h60
  text "+/-" at 13778,5516.23 h60
  text "3" at 14017.2,5515.17 h60
  text "MIL" at 14133.46,5515.17 h60
  text "MATERIAL:" at 11333.46,5377.52 h60
  text "FR-4 High Tg" at 12319.9,5249 h60
  text "X" at 12175.46,5241.01 h60
  text "FR-408" at 11754.46,5236.49 h60
  text "OTHER" at 13242.46,5236.49 h60
  text "62 MIL (1.6mm) +/-10%" at 12074.56,5093.46 h60
  text "X" at 11954.46,5091.01 h60
  text "THICKNESS:" at 11408.23,5085.24 h60
  text "OTHER" at 13359.46,5085.24 h60
  text "TOLERANCE:" at 11408.23,4946.92 h60
  text "X" at 12256.46,4946.92 h60
  text "ANSI IPC-6012 TYPE 3 CLASS 2" at 12434.48,4946.92 h60
  text "OTHER +/-" at 12434.46,4802.73 h60
  text "BOW & TWIST:" at 11408.23,4657.54 h60
  text "X" at 12256.46,4657.54 h60
  text "ANSI IPC-6012 TYPE 3 CLASS 2" at 12434.48,4657.54 h60
  text "OTHER +/-" at 12434.46,4510.85 h60
  text "DRILLING:" at 11333.46,4380.23 h60
  text "NC_DRILL FILES" at 13094.46,4275.04 h60
  text "REFERENCE:" at 11408.23,4271.1 h60
  text "X" at 12065.46,4271.01 h60
  text "AS SHOWN" at 12243.46,4271.1 h60
  text "X" at 12966.46,4271.1 h60
  text "OTHER" at 13392.46,4128.85 h60
  text "PTH COPPER THICKNESS:" at 11407.91,4125.32 h60
  text "X" at 12547.14,4125.32 h60
  text "20-30 um" at 12675.14,4125.32 h60
  text "BOARD FINISH:" at 11333.46,3977.73 h60
  text "SILKSCREEN:" at 11488.68,3867.6 h60
  text "X" at 12446.46,3867.6 h60
  text "TOP" at 12563.46,3867.6 h60
  text "X" at 12956.46,3867.6 h60
  text "BOTTOM" at 13074.46,3867.6 h60
  text "SILKSCREEN COLOR:" at 11488.68,3712.41 h60
  text "X" at 12445.46,3712.41 h60
  text "WHITE" at 12563.46,3712.41 h60
  text "OTHER" at 13074.46,3712.41 h60
  text "X" at 12576.46,3568.96 h60
  text "GREEN" at 12694.46,3568.96 h60
  text "OTHER" at 13312.46,3568.96 h60
  text "SOLDER RESIST COLOR:" at 11488.68,3562.1 h60
  text "X" at 12576.46,3414.71 h60
  text "MATTE" at 12694.46,3414.71 h60
  text "SEMI-GLOSS" at 13312,3414.07 h60
  text "IMMERSION GOLD (ENIG)" at 12394.46,3241.94 h60
  text "ENEPIG" at 13732,3234.72 h60
  text "SURFACE FINISH:" at 11333.46,3233.72 h60
  text "X" at 12216.46,3233.72 h60
  text "IMM. TIN/SILVER OR EQUIV" at 11663,3096.4 h60
  text "OTHER" at 13094.46,3092.47 h60
  text "ARRAY/PANEL:" at 11333.46,2937.09 h60
  text "CUT AND TRIM PER M1 BOARD OUTLINE" at 12394.46,2928.87 h60
  text "N.C. ROUTE" at 12394.46,2792.9 h60
  text "X" at 13082.46,2792.9 h60
  text "V. SCORE" at 13260.46,2792.9 h60
  text "CERTIFICATION:" at 11333.46,2663.77 h60
  text "MATERIALS AND WORKMANSHIP FOR ALL PCBS" at 12058.46,2663.77 h60
  text "TO MEET OR EXCEED THE REQUIREMENTS OF:" at 12058.46,2569.71 h60
  text "X" at 11695.97,2441.08 h60
  text "ANSI IPC-A-600F CLASS ->" at 11823.96,2441.08 h60
  text "X" at 13471.97,2441.08 h60
  text "2" at 13581.96,2441.08 h60
  text "1" at 13266.96,2439.58 h60
  text "3" at 13935.96,2439.58 h60
  text "X" at 12507.97,2293.39 h60
  text "RoHS" at 12635.96,2293.39 h60
  text "OTHER" at 13280.36,2293.39 h60
  text "PER ORDER" at 13677.42,2293.39 h60
  text "ALL BOARDS MUST MEET OR EXCEED UL94-V0 REQUIREMENTS." at 11361,2139.57 h60
  text "PCB MUST BEAR THE UL94V-0 UL REGISTERED MATERIAL ID NUMBER" at 11361,2023.5 h60
  text "ADDITIONAL REQUIREMENTS:" at 11333.46,1854.08 h60
  text "MICROSECTION:" at 11408.23,1746.95 h60
  text "YES" at 12313.96,1746.95 h60
  text "REQUIRED" at 13175.46,1602.62 h60
  text "BARE BOARD ELEC. TEST:" at 11408.23,1599.76 h60
  text "NONE" at 12713.96,1599.76 h60
  text "X" at 13057.46,1599.76 h60
  text "PER ORDER" at 13767.46,1599.76 h60
  text "XX MIL VIAS REQUIRE NON-CONDUCTIVE FILL AND PLANARIZE" at 11576.38,1394.82 h59
  text "XX MIL VIAS REQUIRE CONDUCTIVE FILL AND PLANARIZE" at 11584.38,1290.84 h60
  text "OUTER XX MIL VIAS REQUIRE 50 OHM SINGLE-ENDED IMPEDANCE" at 11583.39,1127.46 h58
  text "LAYER 2 & 3 (INNER LAYERS) XX MIL WIDE, XX MIL SPACE / TRACES REQUIRE 100 OHM DIFFERENTIAL IMPEDANCE" at 11575.39,891.74 h60
  text ".Layer_Name" at 577,-858.49 h60
M11 Gerber Information:
  lines w10: -292,-930.17 6308,-930.17 ; -292,-726.83 6310,-726.83 ; -292,-523.5 -292,-1133.5 3713,-1133.5 6310,-1133.5 6310,-523.5 -291.5,-523.5 -291.5,-1133.5 1284,-1133.5 ; 2173,-1133.5 2173,-523.5 ; 3440,-726.83 3440,-523.5 ; 4280,-726.83 4280,-523.5 ; 4902,-1140 4902,-937.17
  text "ALL ARTWORK VIEWED FROM TOP SIDE" at -228.5,-655.67 h60
  text "BOARD #:" at 2248,-655.67 h60
  text ".PRJ_Number" at 2793.5,-655.67 h60
  text "REV:" at 3638,-655.67 h60
  text ".PCB_Rev" at 3929.5,-655.67 h60
  text "SVN REV:" at 4476,-655.67 h60
  text ".VersionControl_RevNumber" at 4982,-655.67 h60
  text "LAYER NAME =" at -228.5,-858.49 h60
  text "TID #:" at 2248,-859 h60
  text ".TID" at 2793.5,-859 h60
  text "PLOT NAME =" at -228.5,-1064.34 h60
  text ".plot_File_Name" at 577,-1064.34 h60
  text "GENERATED    :" at 2250,-1064.34 h60
  text ".Print_Date" at 3119.5,-1064.34 h60
  text ".Print_Time" at 3848.5,-1064.34 h60
  text "TEXAS INSTRUMENTS" at 5113,-1064.34 h60
M12 Stackup:
  drawing of 191 lines, arcs and shapes, not listed
  text "Layer" at 9797.84,7627.5 h60
  text "Name" at 10207.76,7627.5 h60
  text "Material" at 11137.5,7627.5 h60
  text "Thickness" at 11997.27,7627.5 h60
  text "Constant" at 12647.1,7627.5 h60
  text "Board Layer Stack" at 13216.96,7627.5 h60
  text "1" at 9797.84,7507.5 h60
  text "Top Overlay" at 10207.76,7507.5 h60
  text "2" at 9797.84,7387.5 h60
  text "Top Solder" at 10207.76,7387.5 h60
  text "Solder Resist" at 11137.5,7387.5 h60
  text "0.40mil" at 11997.27,7387.5 h60
  text "3.5" at 12647.1,7387.5 h60
  text "3" at 9797.84,7267.5 h60
  text "Top Layer" at 10207.76,7267.5 h60
  text "Copper" at 11137.5,7267.5 h60
  text "1.40mil" at 11997.27,7267.5 h60
  text "4" at 9797.84,7147.5 h60
  text "Dielectric1" at 10207.76,7147.5 h60
  text "FR-4" at 11137.5,7147.5 h60
  text "59.20mil" at 11997.27,7147.5 h60
  text "4.8" at 12647.1,7147.5 h60
  text "5" at 9797.84,7027.5 h60
  text "Bottom Layer" at 10207.76,7027.5 h60
  text "Copper" at 11137.5,7027.5 h60
  text "1.40mil" at 11997.27,7027.5 h60
  text "6" at 9797.84,6907.5 h60
  text "Bottom Solder" at 10207.76,6907.5 h60
  text "Solder Resist" at 11137.5,6907.5 h60
  text "0.40mil" at 11997.27,6907.5 h60
  text "3.5" at 12647.1,6907.5 h60
  text "7" at 9797.84,6787.5 h60
  text "Bottom Overlay" at 10207.76,6787.5 h60
  text ".Layer_Name" at 577,-858.49 h60
M13 Component Bodies Top:
  text ".Layer_Name" at 577,-858.49 h60
M14 Component Bodies Bottom:
  text ".Layer_Name" at 577,-858.49 h60
M15 Courtyards Top:
  text ".Layer_Name" at 577,-858.49 h60
M16 Courtyards Bottom:
  text ".Layer_Name" at 577,-858.49 h60
Drill Drawing:
  circle w10: c5363.72,3320.28 r27.63
  lines w10: 5336.09,2919.7 5391.34,2919.7 5391.34,2974.95 5336.09,2974.95 5336.09,2919.7 ; 5336.09,3057.83 5349.9,3057.83 5363.72,3044.02 5377.53,3057.83 5391.34,3057.83 5377.53,3071.64 5391.34,3085.46 5377.53,3085.46 5363.72,3099.27 5349.9,3085.46 5336.09,3085.46 5349.9,3071.64 5336.09,3057.83 ; 5336.09,3223.59 5391.34,3223.59 5363.72,3168.34 5336.09,3223.59
  lines w12: 5286,2882.4 8517.49,2882.4 ; 5286,3379.68 8517.49,3379.68 ; 5623.86,2758.08 5623.86,3504 ; 5955.86,2758.08 5955.86,3504 ; 6592.43,2758.08 6592.43,3504 ; 6851.57,2758.08 6851.57,3504 ; 7226.72,2758.08 7226.72,3504 ; 7951.05,2758.08 7951.05,3504 ; 5286,2758.08 8517.49,2758.08 8517.49,3504 5286,3504 5286,2758.08
  text "Symbol" at 5360.59,3416.98 h72
  text "Quantity" at 5661.16,3416.98 h72
  text "Finished Hole Size" at 5993.16,3416.98 h72
  text "Plated" at 6629.72,3416.98 h72
  text "Hole Type" at 6888.86,3416.98 h72
  text "Drill Layer Pair" at 7264.02,3416.98 h72
  text "Hole Tolerance" at 7988.35,3416.98 h72
  text "20" at 5661.16,3292.66 h60
  text "7.87mil (0.200mm)" at 5993.16,3292.66 h60
  text "PTH" at 6629.72,3292.66 h60
  text "Round" at 6888.86,3292.66 h60
  text "Top Layer - Bottom Layer" at 7264.02,3292.66 h60
  text "104" at 5661.16,3168.34 h60
  text "12.00mil (0.305mm)" at 5993.16,3168.34 h60
  text "PTH" at 6629.72,3168.34 h60
  text "Round" at 6888.86,3168.34 h60
  text "Top Layer - Bottom Layer" at 7264.02,3168.34 h60
  text "4" at 5661.16,3044.02 h60
  text "20.00mil (0.508mm)" at 5993.16,3044.02 h60
  text "PTH" at 6629.72,3044.02 h60
  text "Round" at 6888.86,3044.02 h60
  text "Top Layer - Bottom Layer" at 7264.02,3044.02 h60
  text "9" at 5661.16,2919.7 h60
  text "35.43mil (0.900mm)" at 5993.16,2919.7 h60
  text "PTH" at 6629.72,2919.7 h60
  text "Round" at 6888.86,2919.7 h60
  text "Top Layer - Bottom Layer" at 7264.02,2919.7 h60
  text "137 Total" at 5661.16,2795.38 h60
  text ".Layer_Name" at 577,-858.49 h60
M17 Embedded Cavity:
  text ".Layer_Name" at 577,-858.49 h60
M18 Embedded Assembly:
  text ".Layer_Name" at 577,-858.49 h60
M19 Embedded Keepout:
  text ".Layer_Name" at 577,-858.49 h60

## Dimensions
0,0 to -5.01,0 on M2 Board Dimensions
0,0 to 4.93,2760.92 on M2 Board Dimensions
0,-400 to 1000,-400 on M2 Board Dimensions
